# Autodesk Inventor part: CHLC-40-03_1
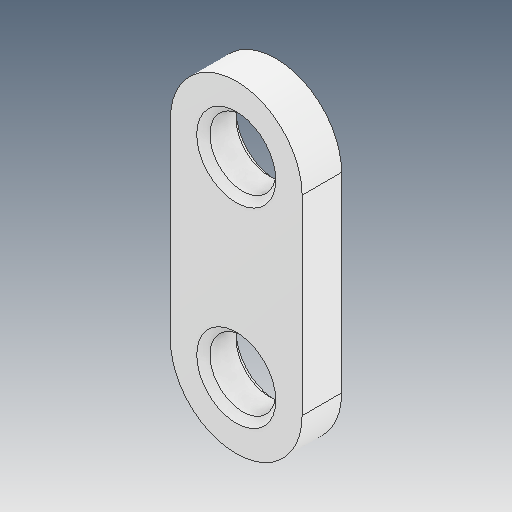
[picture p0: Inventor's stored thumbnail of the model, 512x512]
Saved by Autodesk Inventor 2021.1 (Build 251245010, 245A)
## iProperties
Created: 2021-05
Part Number: CHLC-40-03_1
Material: Ogólny
Document SubType Name: Modeling
Designer: user
Density: 1 g/cm^3
Appearance: Domyślna
Author: user
Revision Number: ÈÎºÎ
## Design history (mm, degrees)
feature "ÊäÈë1"
node "Bryła1"
